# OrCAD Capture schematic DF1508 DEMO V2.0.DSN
size Custom; title: DF1508 DEMOBOARD; rev: 2.0; note: Sean Chen
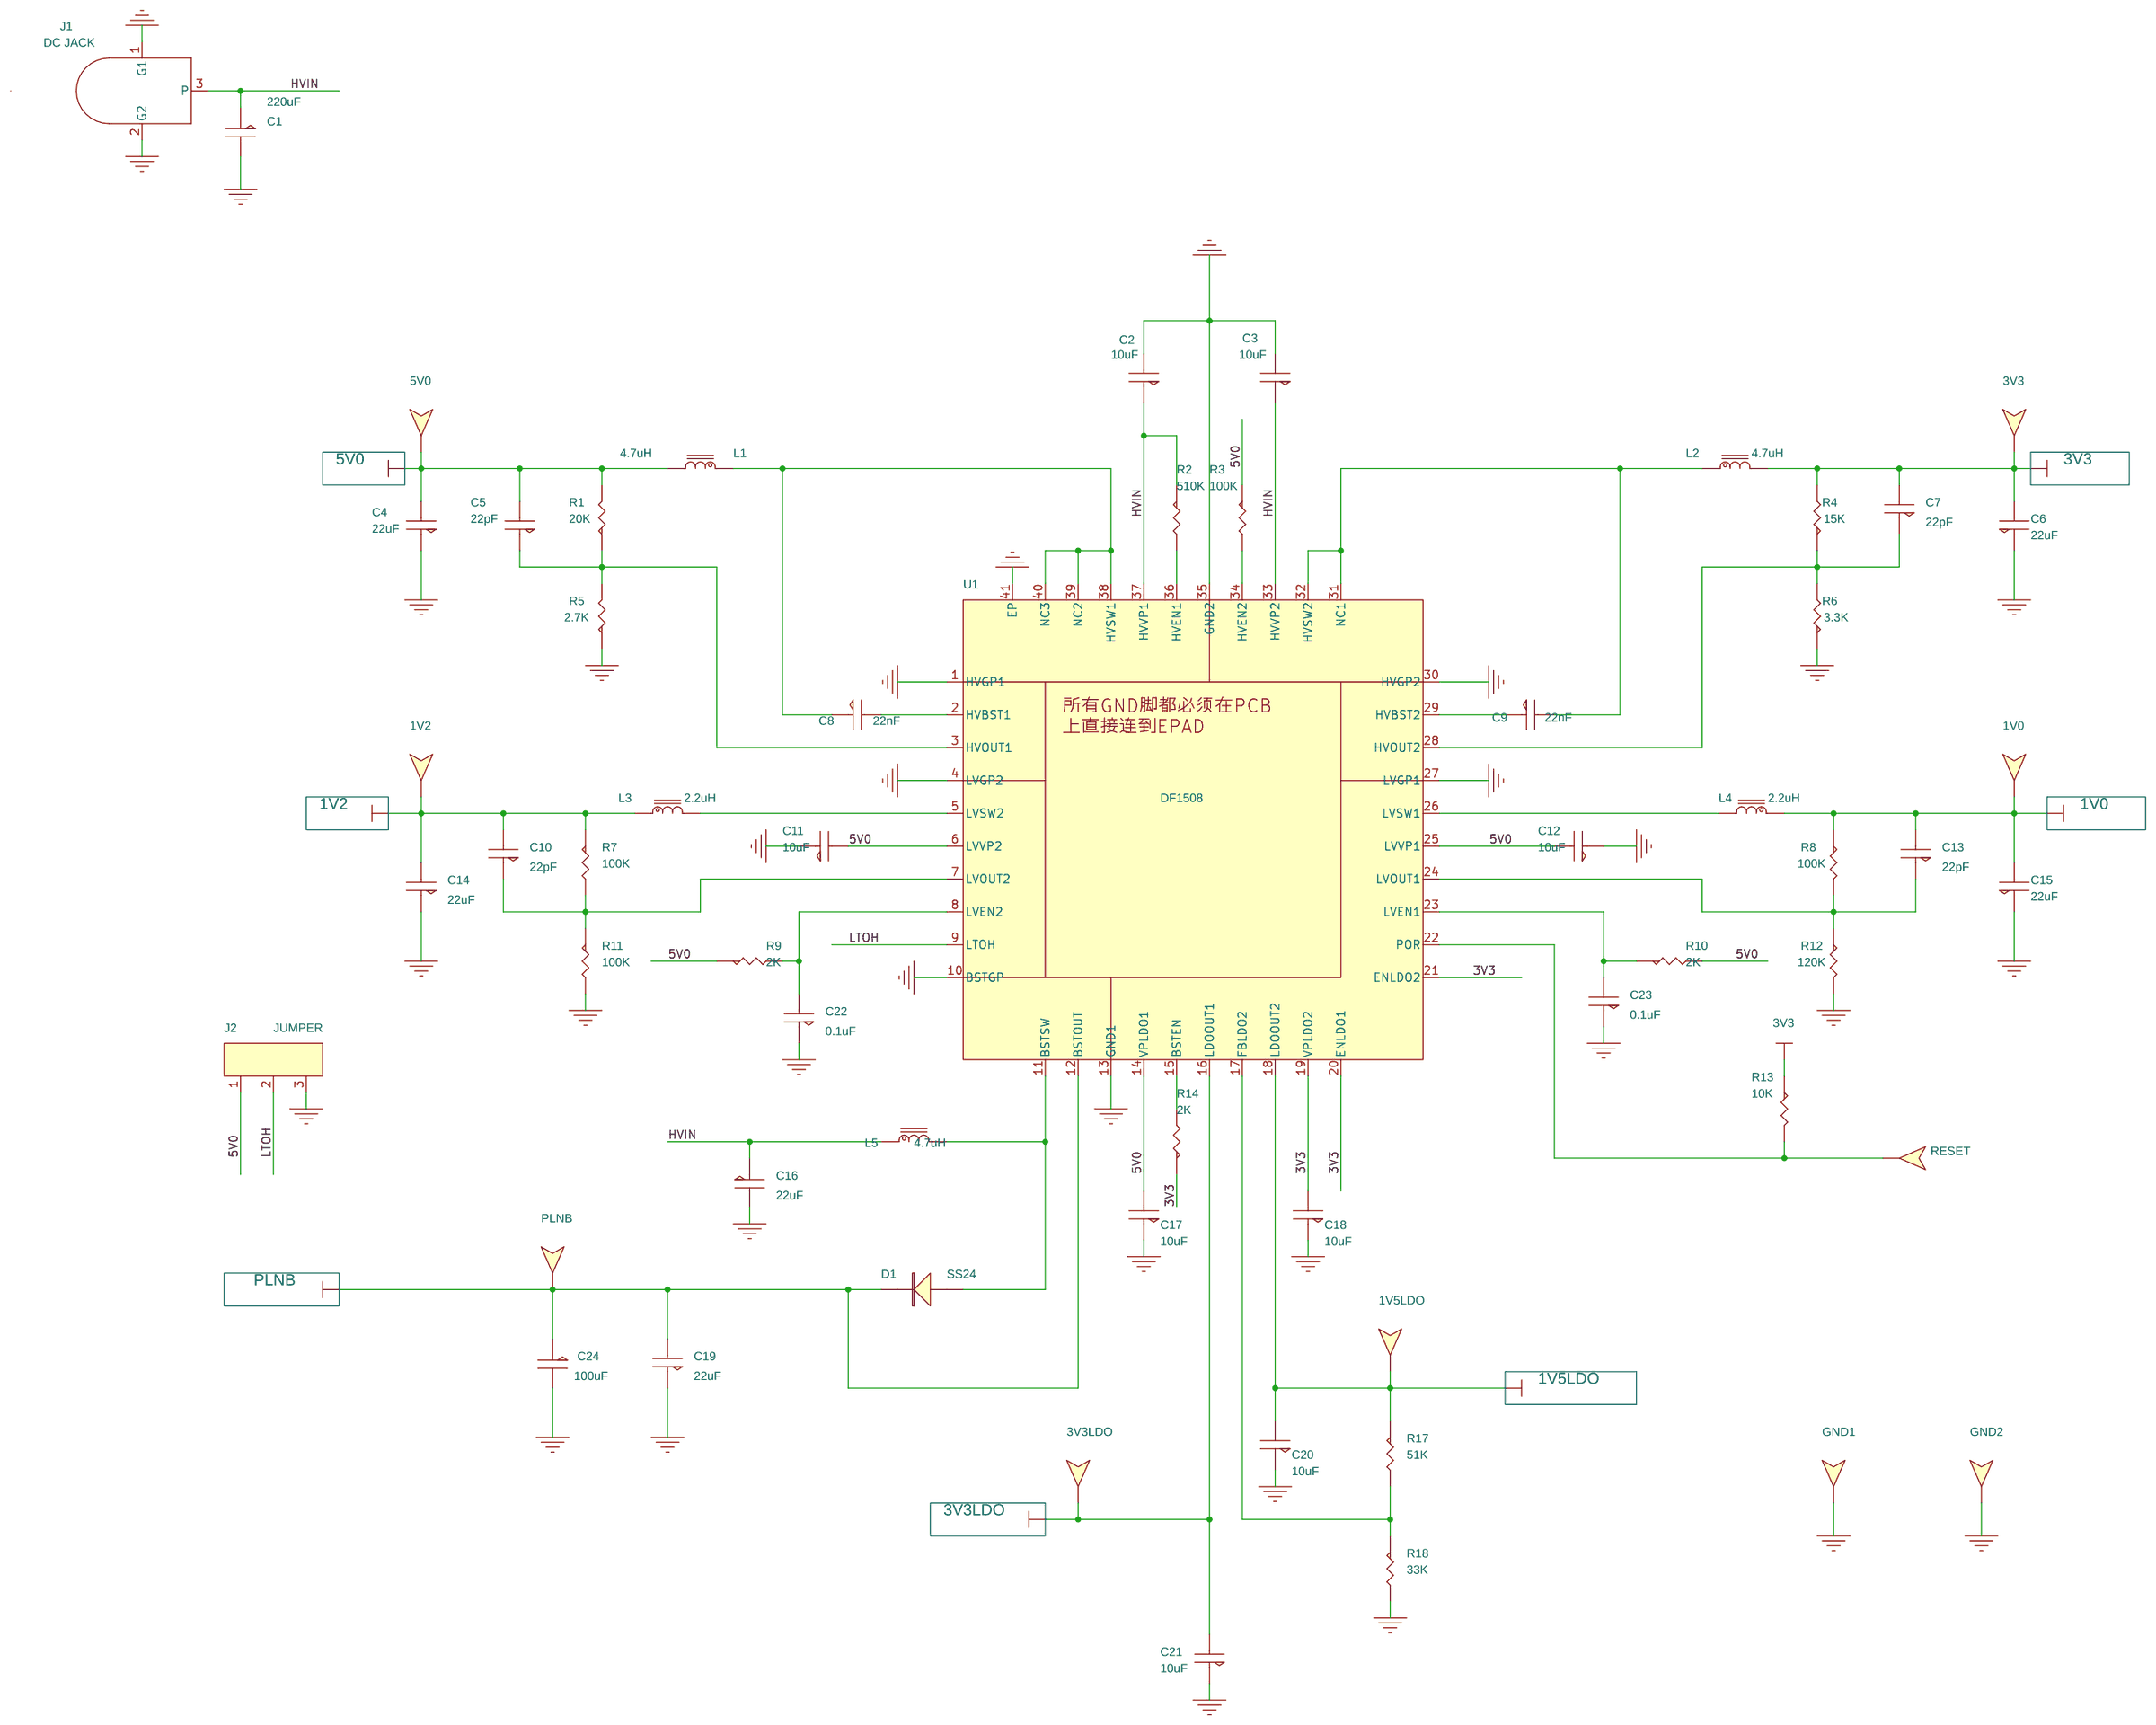
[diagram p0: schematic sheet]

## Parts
1V0  AS_TPWR  [TPD]
1V2  AS_TPWR  [TPD]
1V5LDO  AS_TPWR  [TPD]
3V3  AS_TPWR  [TPD]
3V3LDO  AS_TPWR  [TPD]
5V0  AS_TPWR  [TPD]
C1  220uF  [RB2.5/7]
C2  10uF  [0805]
C3  10uF  [0805]
C4  22uF  [0805]
C5  22pF  [0402]
C6  22uF  [0805]
C7  22pF  [0402]
C8  22nF  [0402]
C9  22nF  [0402]
C10  22pF  [0402]
C11  10uF  [0603]
C12  10uF  [0603]
C13  22pF  [0402]
C14  22uF  [0805]
C15  22uF  [0805]
C16  22uF  [0805]
C17  10uF  [0603]
C18  10uF  [0603]
C19  22uF  [0805]
C20  10uF  [0603]
C21  10uF  [0603]
C22  0.1uF  [0402]
C23  0.1uF  [0402]
C24  100uF  [RB2.5/7]
D1  SS24  [SMA]
GND1  AS_TPWR  [TPD]
GND2  AS_TPWR  [TPD]
J1  DC JACK  [CON_BARREL]
J2  JUMPER  [HEADER3]
L1  4.7uH  [L_4X4]
L2  4.7uH  [L_4X4]
L3  2.2uH  [L_4X4]
L4  2.2uH  [L_4X4]
L5  4.7uH  [L_4X4]
PLNB  AS_TPWR  [TPD]
R1  20K  [0402]
R2  510K  [0402]
R3  100K  [0402]
R4  15K  [0402]
R5  2.7K  [0402]
R6  3.3K  [0402]
R7  100K  [0402]
R8  100K  [0402]
R9  2K  [0402]
R10  2K  [0402]
R11  100K  [0402]
R12  120K  [0402]
R13  10K  [0402]
R14  2K  [0603]
R17  51K  [0402]
R18  33K  [0402]
RESET  AS_TPWR  [TPD]
U1  DF1508  [QFN40]

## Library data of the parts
1V0 1V2 1V5LDO 3V3 3V3LDO 5V0 GND1 GND2 PLNB RESET = AS_TPWR
C1-C24 = CAPNP
D1 = DIODE
J1 = POWER_CON3
J2 = CON3
L1-L5 = INDUCTOR
R1-R14 = R
R17 R18 = R: option: ns
U1 = DF1508

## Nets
1V0: 1V0.1(TP) C13.2 C15.2 L4.1 R8.1
1V2: 1V2.1(TP) C10.2 C14.2 L3.1 R7.1
1V5LDO: 1V5LDO.1(TP) C20.2 R17.1 U1.18(LDOOUT2)
3V3: 3V3.1(TP) C6.2 C7.2 C18.2 L2.2 R4.2 R13.1 R14.1 U1.19(VPLDO2) U1.20(ENLDO1) U1.21(ENLDO2)
3V3LDO: 3V3LDO.1(TP) C21.2 U1.16(LDOOUT1)
5V0: 5V0.1(TP) C4.2 C5.2 C11.2 C12.2 C17.2 J2.1 L1.2 R1.2 R3.1 R9.1 R10.2 U1.6(LVVP2) U1.14(VPLDO1) U1.25(LVVP1)
GND: C1.2 C2.2 C3.2 C4.1 C6.1 C11.1 C12.1 C14.1 C15.1 C16.2 C17.1 C18.1 C19.1 C20.1 C21.1 C22.1 C23.1 C24.2 GND1.1(TP) GND2.1(TP) J1.1(G1) J1.2(G2) J2.3 R5.1 R6.1 R11.2 R12.2 R18.2 U1.1(HVGP1) U1.4(LVGP2) U1.10(BSTGP) U1.13(GND1) U1.27(LVGP1) U1.30(HVGP2) U1.35(GND2) U1.41(EP)
HVIN: C1.1 C2.1 C3.1 C16.1 J1.3(P) L5.1 R2.1 U1.33(HVVP2) U1.37(HVVP1)
LTOH: J2.2 U1.9(LTOH)
PLNB: C19.2 C24.1 D1.2(C) PLNB.1(TP) U1.12(BSTOUT)
N46671: C10.1 R7.2 R11.1 U1.7(LVOUT2)
N47440: D1.1(A) L5.2 U1.11(BSTSW)
N47975: R13.2 RESET.1(TP) U1.22(POR)
N48232: C13.1 R8.2 R12.1 U1.24(LVOUT1)
N48310: L4.2 U1.26(LVSW1)
N49415: C7.1 R4.1 R6.2 U1.28(HVOUT2)
N92471: C5.1 R1.1 R5.2 U1.3(HVOUT1)
N93462: C8.1 L1.1 U1.38(HVSW1) U1.39(NC2) U1.40(NC3)
N93473: C9.2 L2.1 U1.31(NC1) U1.32(HVSW2)
N94013: C8.2 U1.2(HVBST1)
N94029: C9.1 U1.29(HVBST2)
N97846: L3.2 U1.5(LVSW2)
N109298: R17.2 R18.1 U1.17(FBLDO2)
N124673: R2.2 U1.36(HVEN1)
N124758: R3.2 U1.34(HVEN2)
N126504: R14.2 U1.15(BSTEN)
N133824: C22.2 R9.2 U1.8(LVEN2)
N134039: C23.2 R10.1 U1.23(LVEN1)
